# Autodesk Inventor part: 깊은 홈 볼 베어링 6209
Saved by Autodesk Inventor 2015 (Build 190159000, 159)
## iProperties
Created: 2025-06
Part Number: 깊은 홈 볼 베어링 6209
Material: 일반
Document SubType Name: Modeling
Designer: 104
Density: 1 g/cm^3
Appearance: 기본값
Author: 104
Author: jhkim
Description: 깊은 그루부 볼 베어링
Creation Date: 2025-05-23
Sending System: Autodesk Inventor 2026
Preprocessor: ST-DEVELOPER v20.1
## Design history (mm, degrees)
node "깊은 홈 볼 베어링 62091"
body "Solid1"
node "Solid1_1"
node "Solid1_2"
node "Solid1_3"
node "Solid1_4"
node "Solid1_5"
node "Solid1_6"
node "Solid1_7"
node "Solid1_8"
node "Solid1_9"
node "Solid1_10"
node "Solid1_11"
node "기준1"
node "기준2"
node "기준3"
node "기준4"
node "기준5"
node "기준6"
node "기준7"
node "기준8"
node "기준9"
node "기준10"
node "기준11"
node "기준12"
